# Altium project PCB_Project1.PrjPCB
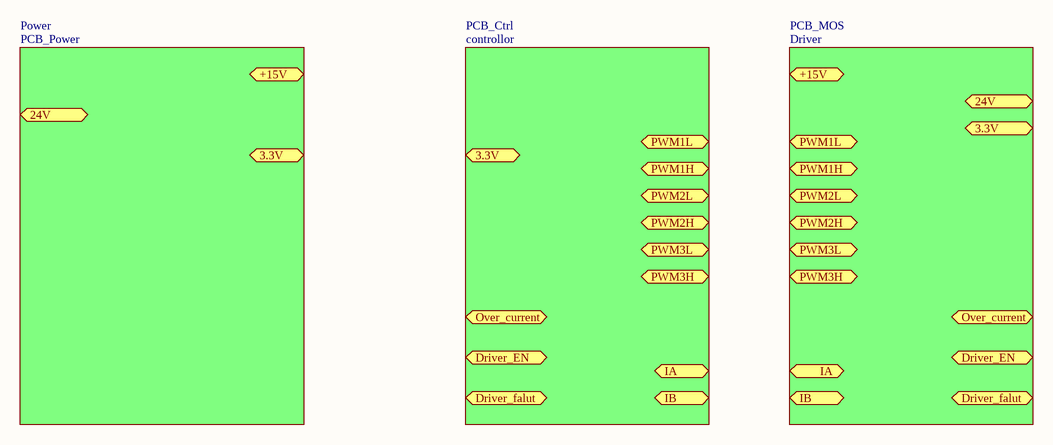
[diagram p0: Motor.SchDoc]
4 sheets, 112 parts. Net scope: flat (ports and power ports of the same name join across sheets).
Sheets:
  Motor.SchDoc
    PCB_Power = Power.SchDoc
    PCB_Ctrl = controllor.SchDoc
    PCB_MOS = Driver.SchDoc

## Sheet Motor.SchDoc
size A4

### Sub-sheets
PCB_Ctrl = controllor: no entries
PCB_MOS = Driver: no entries
PCB_Power = Power: no entries

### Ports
3.3V, 24V, +15V, Driver_EN, Driver_falut, IA, IB, Over_current, PWM1H, PWM1L, PWM2H, PWM2L, PWM3H, PWM3L

## Sheet Power.SchDoc
size A4
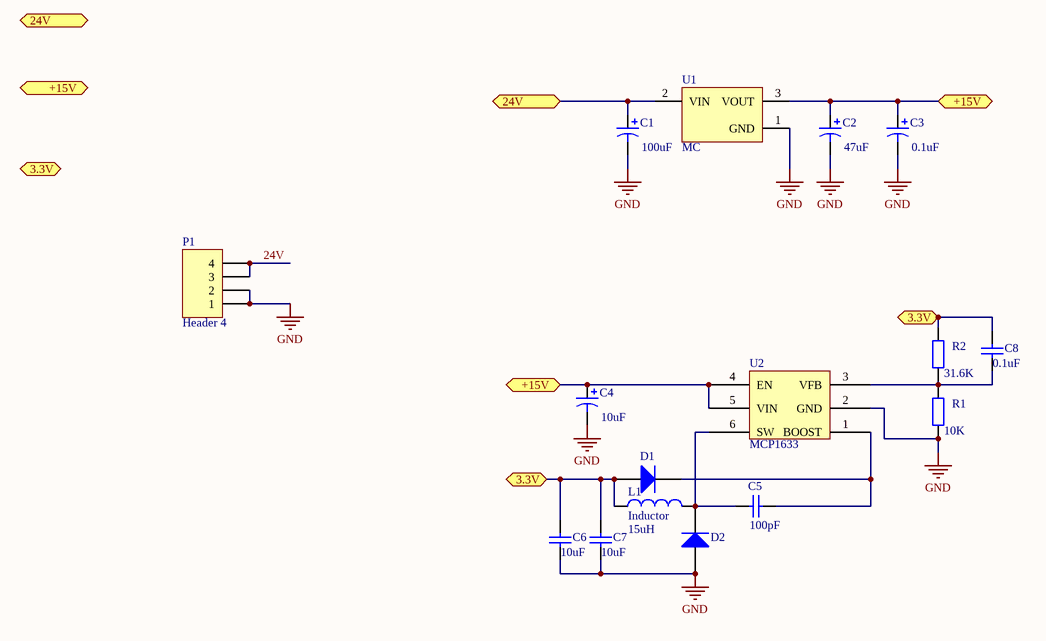
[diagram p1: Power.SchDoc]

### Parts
C1  value 100uF  [RB7.6-15]
C2  value 47uF  [RB7.6-15]
C3  value 0.1uF  [RB7.6-15]
C4  value 10uF  [RB7.6-15]
C5  value 100pF  [C1206]
C6  value 10uF  [C1206]
C7  value 10uF  [C1206]
C8  value 0.1uF  [C1206]
D1  (no value)  [SMC]
D2  (no value)  [SMC]
L1  Inductor  value 15uH  [INDC3216]
P1  Header 4  [HDR1X4]
R1  value 10K  [AXIAL-0.4]  (hidden comment: Res2)
R2  value 31.6K  [AXIAL-0.4]  (hidden comment: Res2)
U1  MC  [TO-92-TO3]
U2  MCP1633

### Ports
3.3V, 24V, +15V

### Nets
GND: C1.2 C2.2 C3.2 C4.2 C6.2 C7.2 D2.1(A) P1.1 P1.2 R1.1 U1.1(GND) U2.2(GND)
24V: P1.3 P1.4
NetC1_1: C1.1 U1.2(VIN) ; port 24V
NetC2_1: C2.1 C3.1 C4.1 U1.3(VOUT) U2.4(EN) U2.5(VIN) ; port +15V
NetC5_1: C5.1 D2.2(K) L1.2 U2.6(SW)
NetC5_2: C5.2 D1.2(K) U2.1(BOOST)
NetC6_1: C6.1 C7.1 C8.1 D1.1(A) L1.1 R2.2 ; port 3.3V
NetC8_2: C8.2 R1.2 R2.1 U2.3(VFB)

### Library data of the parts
C1-C4 = Cap Pol1: Polarized Capacitor (Radial)
C5-C8 = Cap Semi: Capacitor (Semiconductor SIM Model)
D1 D2 = Diode: Default Diode
L1 = Inductor: Code_IEC: 1005
P1 = Header 4: Header, 4-Pin
R1 R2 = Res2: Resistor
U1 = MCP1700-1302E/TO: Low Quiescent Current LDO, 3-Pin TO-92, Extended TemperatureBAG; Manufacturer: Microchip

## Sheet controllor.SchDoc
size A4
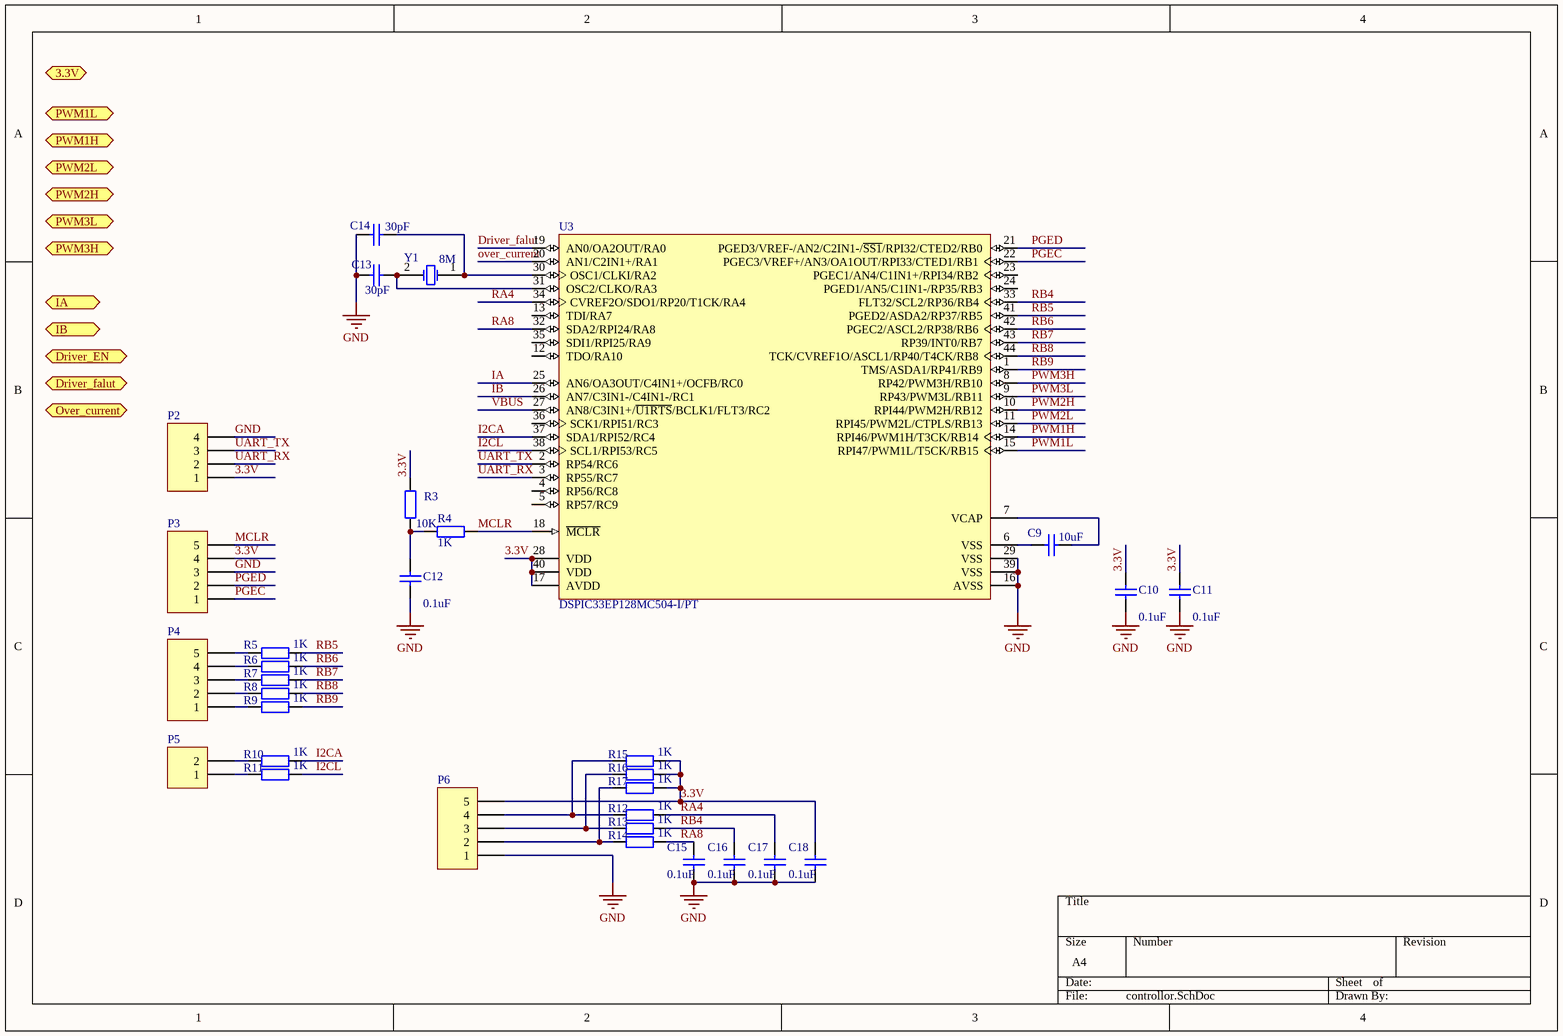
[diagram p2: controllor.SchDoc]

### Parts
(Parts that share a designator on the sheet are numbered #1, #2 ... from top to bottom, then left to right.)
C9  value 10uF  [C1206]
C10  value 0.1uF  [C1206]
C11  value 0.1uF  [C1206]
C12  value 0.1uF  [C1206]
C13  value 30pF  [C1206]
C14  value 30pF  [C1206]
C15  value 0.1uF  [C1206]
C16  value 0.1uF  [C1206]
C17  value 0.1uF  [C1206]
C18  value 0.1uF  [C1206]
P2  Header 4  [HDR1X4]  (value not drawn)
P3  Header 5  [HDR1X5]  (value not drawn)
P4  Header 5  [HDR1X5]  (value not drawn)
P5  Header 2  [HDR1X2]  (value not drawn)
P6  Header 5  [HDR1X5]  (value not drawn)
R3  value 10K  [AXIAL-0.4]  (hidden comment: Res2)
R4  value 1K  [AXIAL-0.4]  (hidden comment: Res2)
R5  value 1K  [AXIAL-0.4]  (hidden comment: Res2)
R6  value 1K  [AXIAL-0.4]  (hidden comment: Res2)
R7  value 1K  [AXIAL-0.4]  (hidden comment: Res2)
R8  value 1K  [AXIAL-0.4]  (hidden comment: Res2)
R9  value 1K  [AXIAL-0.4]  (hidden comment: Res2)
R10  value 1K  [AXIAL-0.4]  (hidden comment: Res2)
R11  value 1K  [AXIAL-0.4]  (hidden comment: Res2)
R12  value 1K  [AXIAL-0.4]  (hidden comment: Res2)
R13  value 1K  [AXIAL-0.4]  (hidden comment: Res2)
R14  value 1K  [AXIAL-0.4]  (hidden comment: Res2)
R15  value 1K  [AXIAL-0.4]  (hidden comment: Res2)
R16  value 1K  [AXIAL-0.4]  (hidden comment: Res2)
R17#1  value 1K  [AXIAL-0.4]  (hidden comment: Res2)
U3  DSPIC33EP128MC504-I/PT  [MCHP-TQFP-PT44_N]
Y1  value 8M  [R38]  (hidden comment: XTAL)

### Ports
3.3V, Driver_EN, Driver_falut, IA, IB, Over_current, PWM1H, PWM1L, PWM2H, PWM2L, PWM3H, PWM3L

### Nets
GND: C10.1 C11.1 C12.1 C13.2 C14.2 C15.1 C16.1 C17.1 C18.1 P2.4 P3.3 P6.1 U3.16(AVSS) U3.29(VSS) U3.39(VSS)
3.3V: C10.2 C11.2 C18.2 P2.1 P3.4 P6.5 R3.2 R15.1 R16.1 R17#1.1 U3.17(AVDD) U3.28(VDD) U3.40(VDD)
Driver_falut: U3.19(AN0/OA2OUT/RA0)
I2CA: R10.1 U3.37(SDA1/RPI52/RC4)
I2CL: R11.1 U3.38(SCL1/RPI53/RC5)
IA: U3.25(AN6/OA3OUT/C4IN1+/OCFB/RC0)
IB: U3.26(AN7/C3IN1-/C4IN1-/RC1)
MCLR: P3.5 R4.1 U3.18(~{MCLR})
over_current: U3.20(AN1/C2IN1+/RA1)
PGEC: P3.1 U3.22(PGEC3/VREF+/AN3/OA1OUT/RPI33/CTED1/RB1)
PGED: P3.2 U3.21(PGED3/VREF-/AN2/C2IN1-/~{SS1}/RPI32/CTED2/RB0)
PWM1H: U3.14(RPI46/PWM1H/T3CK/RB14)
PWM1L: U3.15(RPI47/PWM1L/T5CK/RB15)
PWM2H: U3.10(RPI44/PWM2H/RB12)
PWM2L: U3.11(RPI45/PWM2L/CTPLS/RB13)
PWM3H: U3.8(RP42/PWM3H/RB10)
PWM3L: U3.9(RP43/PWM3L/RB11)
RA4: C17.2 R12.1 U3.34(CVREF2O/SDO1/RP20/T1CK/RA4)
RA8: C15.2 R14.1 U3.32(SDA2/RPI24/RA8)
RB4: C16.2 R13.1 U3.33(FLT32/SCL2/RP36/RB4)
RB5: R5.1 U3.41(PGED2/ASDA2/RP37/RB5)
RB6: R6.1 U3.42(PGEC2/ASCL2/RP38/RB6)
RB7: R7.1 U3.43(RP39/INT0/RB7)
RB8: R8.1 U3.44(TCK/CVREF1O/ASCL1/RP40/T4CK/RB8)
RB9: R9.1 U3.1(TMS/ASDA1/RP41/RB9)
UART_RX: P2.2 U3.3(RP55/RC7)
UART_TX: P2.3 U3.2(RP54/RC6)
VBUS: U3.27(AN8/C3IN1+/~{U1RTS}/BCLK1/FLT3/RC2)
NetC9_1: C9.1 U3.6(VSS)
NetC9_2: C9.2 U3.7(VCAP)
NetC12_2: C12.2 R3.1 R4.2
NetC13_1: C13.1 U3.31(OSC2/CLKO/RA3) Y1.2(OSC2)
NetC14_1: C14.1 U3.30(OSC1/CLKI/RA2) Y1.1(OSC1)
NetP4_1: P4.1 R9.2
NetP4_2: P4.2 R8.2
NetP4_3: P4.3 R7.2
NetP4_4: P4.4 R6.2
NetP4_5: P4.5 R5.2
NetP5_1: P5.1 R11.2
NetP5_2: P5.2 R10.2
NetP6_2: P6.2 R14.2 R17#1.2
NetP6_3: P6.3 R13.2 R16.2
NetP6_4: P6.4 R12.2 R15.2

Not connected (* = marked no-connect by the designer): U3 4(RP56/RC8) 5(RP57/RC9) 12(TDO/RA10) 13(TDI/RA7) 23(PGEC1/AN4/C1IN1+/RPI34/RB2) 24(PGED1/AN5/C1IN1-/RP35/RB3) 35(SDI1/RPI25/RA9) 36(SCK1/RPI51/RC3)

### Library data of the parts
C9-C18 = Cap Semi: Capacitor (Semiconductor SIM Model)
P2 = Header 4: Header, 4-Pin
P3 P4 P6 = Header 5: Header, 5-Pin
P5 = Header 2: Header, 2-Pin
R3-R16 R17#1 = Res2: Resistor
U3 = DSPIC33EP128MC504-I/PT: 16-Bit Microcontroller and Digital Signal Controller with High-Speed PWM, Op Amps and Advanced Analog, 70 MIPS, 35 I/O, GPIO, -40 to 85 degC, 44-pin TQFP (PT44), Tray; Manufacturer: Microchip
Y1 = XTAL: Crystal Oscillator

## Sheet Driver.SchDoc
size A4
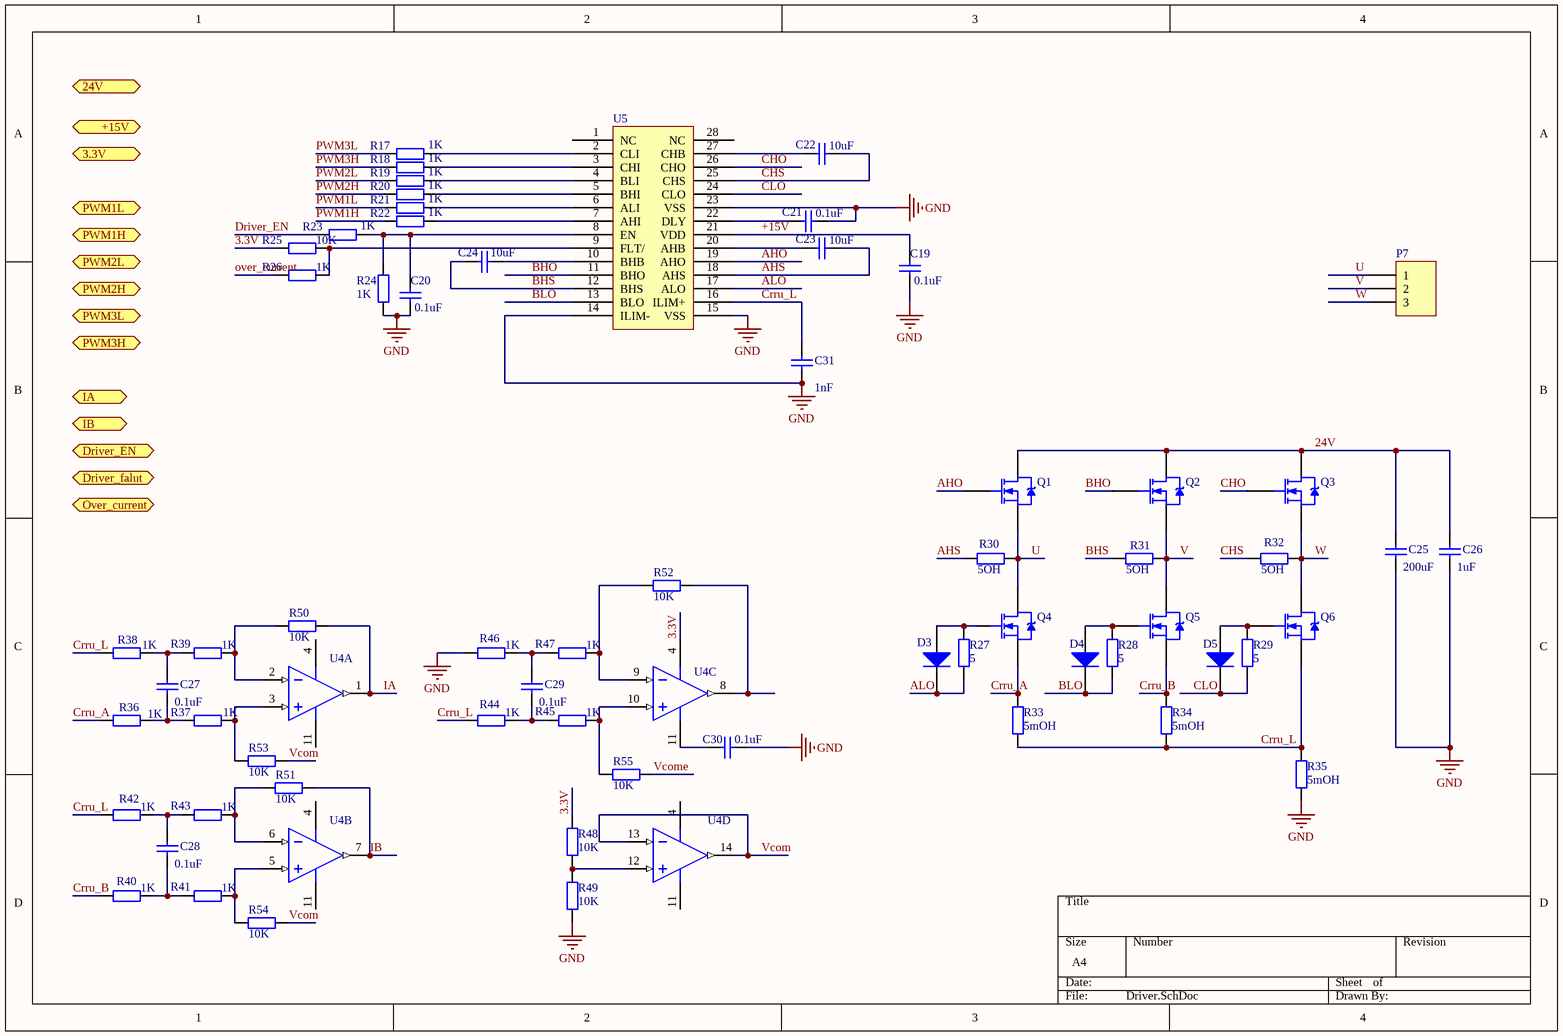
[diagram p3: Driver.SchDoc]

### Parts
(Parts that share a designator on the sheet are numbered #1, #2 ... from top to bottom, then left to right.)
C19  value 0.1uF  [C1206]
C20  value 0.1uF  [C1206]
C21  value 0.1uF  [C1206]
C22  value 10uF  [C1206]
C23  value 10uF  [C1206]
C24  value 10uF  [C1206]
C25  value 200uF  [C1206]
C26  value 1uF  [C1206]
C27  value 0.1uF  [C1206]
C28  value 0.1uF  [C1206]
C29  value 0.1uF  [C1206]
C30  value 0.1uF  [C1206]
C31  value 1nF  [C1206]
D3  Diode BAS16  [SOT-23_N]  (value not drawn)
D4  Diode BAS16  [SOT-23_N]  (value not drawn)
D5  Diode BAS16  [SOT-23_N]  (value not drawn)
P7  Header 3  [HDR1X3]  (value not drawn)
Q1  NMOS-2  [TO-220AB]  (value not drawn)
Q2  NMOS-2  [TO-220AB]  (value not drawn)
Q3  NMOS-2  [TO-220AB]  (value not drawn)
Q4  NMOS-2  [TO-220AB]  (value not drawn)
Q5  NMOS-2  [TO-220AB]  (value not drawn)
Q6  NMOS-2  [TO-220AB]  (value not drawn)
R17#2  value 1K  [AXIAL-0.4]  (hidden comment: Res2)
R18  value 1K  [AXIAL-0.4]  (hidden comment: Res2)
R19  value 1K  [AXIAL-0.4]  (hidden comment: Res2)
R20  value 1K  [AXIAL-0.4]  (hidden comment: Res2)
R21  value 1K  [AXIAL-0.4]  (hidden comment: Res2)
R22  value 1K  [AXIAL-0.4]  (hidden comment: Res2)
R23  value 1K  [AXIAL-0.4]  (hidden comment: Res2)
R24  value 1K  [AXIAL-0.4]  (hidden comment: Res2)
R25  value 10K  [AXIAL-0.4]  (hidden comment: Res2)
R26  value 1K  [AXIAL-0.4]  (hidden comment: Res2)
R27  value 5  [AXIAL-0.4]  (hidden comment: Res2)
R28  value 5  [AXIAL-0.4]  (hidden comment: Res2)
R29  value 5  [AXIAL-0.4]  (hidden comment: Res2)
R30  value 5OH  [AXIAL-0.4]  (hidden comment: Res2)
R31  value 5OH  [AXIAL-0.4]  (hidden comment: Res2)
R32  value 5OH  [AXIAL-0.4]  (hidden comment: Res2)
R33  value 5mOH  [AXIAL-0.4]  (hidden comment: Res2)
R34  value 5mOH  [AXIAL-0.4]  (hidden comment: Res2)
R35  value 5mOH  [AXIAL-0.4]  (hidden comment: Res2)
R36  value 1K  [AXIAL-0.4]  (hidden comment: Res2)
R37  value 1K  [AXIAL-0.4]  (hidden comment: Res2)
R38  value 1K  [AXIAL-0.4]  (hidden comment: Res2)
R39  value 1K  [AXIAL-0.4]  (hidden comment: Res2)
R40  value 1K  [AXIAL-0.4]  (hidden comment: Res2)
R41  value 1K  [AXIAL-0.4]  (hidden comment: Res2)
R42  value 1K  [AXIAL-0.4]  (hidden comment: Res2)
R43  value 1K  [AXIAL-0.4]  (hidden comment: Res2)
R44  value 1K  [AXIAL-0.4]  (hidden comment: Res2)
R45  value 1K  [AXIAL-0.4]  (hidden comment: Res2)
R46  value 1K  [AXIAL-0.4]  (hidden comment: Res2)
R47  value 1K  [AXIAL-0.4]  (hidden comment: Res2)
R48  value 10K  [AXIAL-0.4]  (hidden comment: Res2)
R49  value 10K  [AXIAL-0.4]  (hidden comment: Res2)
R50  value 10K  [AXIAL-0.4]  (hidden comment: Res2)
R51  value 10K  [AXIAL-0.4]  (hidden comment: Res2)
R52  value 10K  [AXIAL-0.4]  (hidden comment: Res2)
R53  value 10K  [AXIAL-0.4]  (hidden comment: Res2)
R54  value 10K  [AXIAL-0.4]  (hidden comment: Res2)
R55  value 10K  [AXIAL-0.4]  (hidden comment: Res2)
U4  MCP6024-E/ST  [TSSOP-ST14_N]  (value not drawn)  (parts A,B,C,D of 4)
U5  MIC4607-1  (value not drawn)

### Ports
3.3V, 24V, +15V, Driver_EN, Driver_falut, IA, IB, Over_current, PWM1H, PWM1L, PWM2H, PWM2L, PWM3H, PWM3L

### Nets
GND: C19.1 C20.1 C21.1 C25.2 C26.2 C30.2 C31.1 R24.2 R35.2 R46.1 R49.1 U5.14(ILIM-) U5.15(VSS) U5.23(VSS)
3.3V: R25.1 R48.2 U4.4(VDD)
24V: C25.1 C26.1 Q1.2(D) Q2.2(D) Q3.2(D)
+15V: C19.2 U5.21(VDD)
AHO: Q1.1(G) U5.19(AHO)
AHS: C23.1 R30.2 U5.18(AHS)
ALO: D3.3(K) R27.1 U5.17(ALO)
BHO: Q2.1(G) U5.11(BHO)
BHS: C24.1 R31.2 U5.12(BHS)
BLO: D4.3(K) R28.1 U5.13(BLO)
CHO: Q3.1(G) U5.26(CHO)
CHS: C22.1 R32.2 U5.25(CHS)
CLO: D5.3(K) R29.1 U5.24(CLO)
Crru_A: Q4.3(S) R33.1 R36.1
Crru_B: Q5.3(S) R34.1 R40.1
Crru_L: C31.2 Q6.3(S) R33.2 R34.2 R35.1 R38.1 R42.1 R44.1 U5.16(ILIM+)
Driver_EN: R23.2
IA: R50.1 U4.1(VOUTA)
IB: R51.1 U4.7(VOUTB)
over_current: R26.1
PWM1H: R22.2
PWM1L: R21.2
PWM2H: R20.2
PWM2L: R19.2
PWM3H: R18.2
PWM3L: R17#2.2
U: P7.1 Q1.3(S) Q4.2(D) R30.1
V: P7.2 Q2.3(S) Q5.2(D) R31.1
Vcom: R53.1 R54.1 U4.13(VIND-) U4.14(VOUTD)
Vcome: R55.1
W: P7.3 Q3.3(S) Q6.2(D) R32.1
NetC20_2: C20.2 R23.1 R24.1 U5.8(EN)
NetC21_2: C21.2 U5.22(DLY)
NetC22_2: C22.2 U5.27(CHB)
NetC23_2: C23.2 U5.20(AHB)
NetC24_2: C24.2 U5.10(BHB)
NetC27_1: C27.1 R38.2 R39.1
NetC27_2: C27.2 R36.2 R37.1
NetC28_1: C28.1 R42.2 R43.1
NetC28_2: C28.2 R40.2 R41.1
NetC29_1: C29.1 R46.2 R47.1
NetC29_2: C29.2 R44.2 R45.1
NetC30_1: C30.1 U4.11(VSS)
NetD3_1: D3.1(A) Q4.1(G) R27.2
NetD4_1: D4.1(A) Q5.1(G) R28.2
NetD5_1: D5.1(A) Q6.1(G) R29.2
NetR17#2_1: R17#2.1 U5.2(CLI)
NetR18_1: R18.1 U5.3(CHI)
NetR19_1: R19.1 U5.4(BLI)
NetR20_1: R20.1 U5.5(BHI)
NetR21_1: R21.1 U5.6(ALI)
NetR22_1: R22.1 U5.7(AHI)
NetR25_2: R25.2 R26.2 U5.9(FLT/)
NetR37_2: R37.2 R53.2 U4.3(VINA+)
NetR39_2: R39.2 R50.2 U4.2(VINA-)
NetR41_2: R41.2 R54.2 U4.5(VINB+)
NetR43_2: R43.2 R51.2 U4.6(VINB-)
NetR45_2: R45.2 R55.2 U4.10(VINC+)
NetR47_2: R47.2 R52.2 U4.9(VINC-)
NetR48_1: R48.1 R49.2 U4.12(VIND+)
NetR52_1: R52.1 U4.8(VOUTC)

Not connected (* = marked no-connect by the designer): U5 1(NC) 28(NC)

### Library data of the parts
C19-C31 = Cap Semi: Capacitor (Semiconductor SIM Model)
D3-D5 = Diode BAS16: Silicon Switching Diode for High-Speed Switching; Note: Pin 2 is not connected and not drawn.
P7 = Header 3: Header, 3-Pin
Q1-Q6 = NMOS-2: N-Channel Power MOSFET; Note: Pin 2 is electrically connected to pin 4.
R17#2 R18-R55 = Res2: Resistor
U4 = MCP6024-E/ST: Rail-to-Rail Input/Output, 10 MHz Operational Amplifier, 14-Pin TSSOP, Extended Temperature; Manufacturer: Microchip

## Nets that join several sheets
GND: Power (12 pins), controllor (15 pins), Driver (14 pins)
